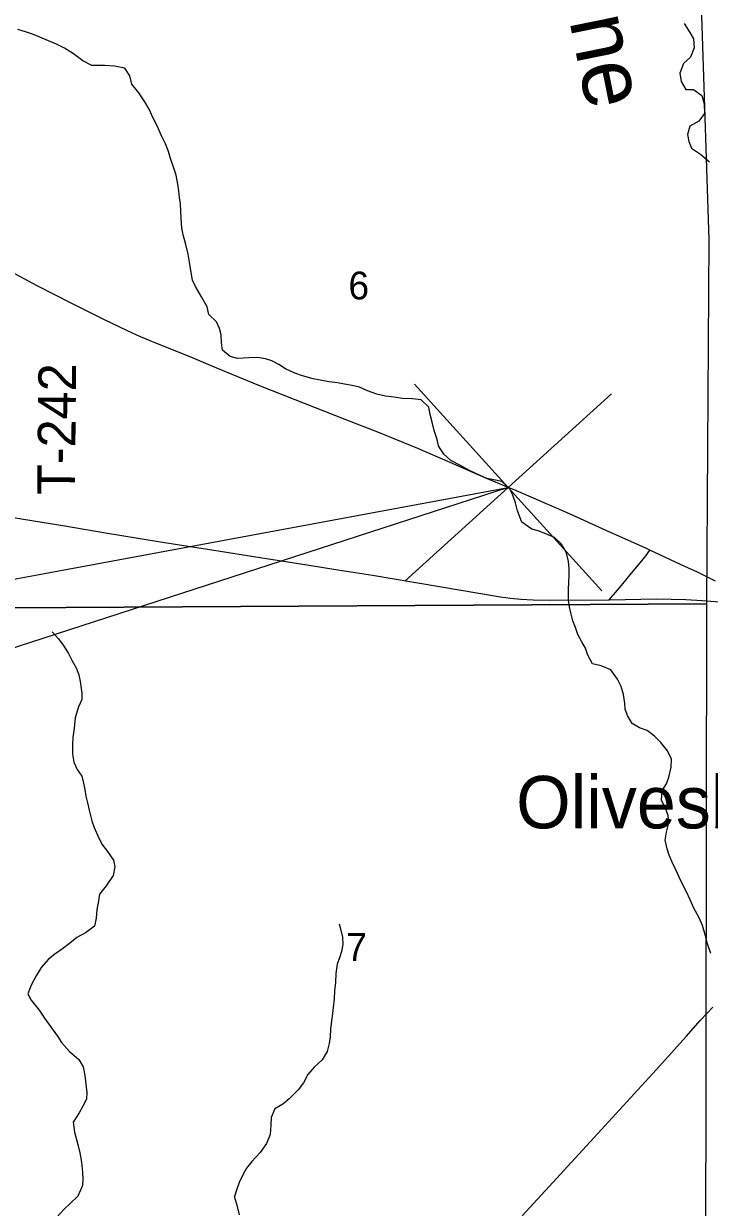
# Model space of a CAD drawing. Extents: x 0 to 70.2, y 0 to 31.4.
# Drawn here: x 4.735 to 5.768, y 16.429 to 18.211 of the extents above; entities that cross this region are included whole.
import ezdxf

# ---------------------------------------------------------------- set-up
doc = ezdxf.new("R2010")
doc.units = 0
for name, color, linetype in [('Default', 7, 'Continuous'), ('GM_X_Minor_River', 7, 'Continuous'), ('GM_X_Minor_River_Text', 7, 'Continuous'), ('GM_X_Section', 7, 'Continuous'), ('GM_X_Section_Text', 7, 'Continuous'), ('GM_X_State_Location', 7, 'Continuous'), ('GM_X_State_Route', 7, 'Continuous'), ('GM_X_Township_Road', 7, 'Continuous'), ('GM_X_Township_Road_Text', 7, 'Continuous'), ('GM_X_Unincorporated_Text', 7, 'Continuous'), ('SH_Data', 7, 'Continuous')]:
    doc.layers.add(name, color=color, linetype=linetype)

msp = doc.modelspace()

# ---------------------------------------------------------------- linework, layer by layer
at = {"layer": 'Default'}
msp.add_lwpolyline([(3.9505, 17.2317), (5.4653, 17.5125), (3.9505, 17.0217)], close=True, dxfattribs=at)
at = {"layer": 'GM_X_Minor_River'}
for points in [[(5.3537, 17.5982), (5.3508, 17.6108), (5.3478, 17.6226), (5.3459, 17.6336), (5.3342, 17.6443), (5.3213, 17.6462), (5.3058, 17.6467), (5.2933, 17.6483), (5.2804, 17.6502), (5.2675, 17.6533), (5.2535, 17.6583), (5.241, 17.6637), (5.23, 17.666), (5.2186, 17.668), (5.208, 17.6699), (5.1951, 17.6715), (5.1818, 17.6739), (5.1712, 17.6762), (5.1553, 17.6808), (5.1436, 17.6847), (5.1296, 17.6912), (5.1197, 17.6977), (5.1091, 17.7034), (5.0993, 17.7065), (5.0875, 17.7085), (5.0742, 17.7078), (5.0572, 17.7067), (5.0462, 17.7098), (5.0348, 17.7194), (5.0334, 17.7304), (5.0327, 17.7425), (5.0304, 17.752), (5.0259, 17.7619), (5.0142, 17.773), (5.0116, 17.7848), (5.0033, 17.7996), (4.9939, 17.8152), (4.9894, 17.8247), (4.9868, 17.8392), (4.985, 17.8517), (4.9832, 17.8639), (4.9794, 17.8783), (4.9753, 17.8928), (4.9735, 17.903), (4.9724, 17.9182), (4.9717, 17.9292), (4.9714, 17.9395), (4.9699, 17.9493), (4.9688, 17.9592), (4.9673, 17.9695), (4.9648, 17.9828), (4.9606, 17.9965), (4.9565, 18.0079), (4.9532, 18.0185), (4.9487, 18.0299), (4.943, 18.0421), (4.9367, 18.0562), (4.9295, 18.0699), (4.9243, 18.082), (4.9179, 18.0931), (4.9084, 18.1068), (4.8983, 18.1201), (4.8949, 18.1323), (4.8874, 18.1441), (4.8718, 18.1472), (4.8574, 18.148), (4.8377, 18.1481), (4.8241, 18.155), (4.8104, 18.1654), (4.7968, 18.1742), (4.7847, 18.1803), (4.7726, 18.1853), (4.7597, 18.1907), (4.7484, 18.1949), (4.7378, 18.1987), (4.7264, 18.2022)], [(5.7305, 18.211), (5.7391, 18.1976), (5.7448, 18.1881), (5.7458, 18.1748), (5.7401, 18.1604), (5.7294, 18.151), (5.724, 18.1366), (5.7259, 18.1237), (5.733, 18.1119), (5.7448, 18.1118), (5.7573, 18.1026), (5.7606, 18.0901), (5.7613, 18.0757), (5.7525, 18.0643), (5.7392, 18.0564), (5.7357, 18.0439), (5.7376, 18.0333), (5.7417, 18.0234), (5.7549, 18.0146), (5.7685, 18.0031)], [(5.7708, 16.8108), (5.7656, 16.8253), (5.7626, 16.8374), (5.7581, 16.853), (5.7532, 16.8644), (5.7453, 16.8793), (5.7393, 16.8914), (5.7341, 16.9036), (5.7284, 16.9143), (5.7228, 16.9257), (5.7183, 16.9356), (5.7126, 16.9485), (5.7081, 16.9588), (5.7051, 16.9683), (5.7018, 16.9816), (5.7037, 16.9933), (5.7076, 17.0074), (5.7065, 17.0184), (5.7024, 17.0294), (5.6964, 17.0412), (5.6972, 17.0564), (5.7041, 17.0662), (5.7072, 17.0765), (5.711, 17.0912), (5.7115, 17.1034), (5.7055, 17.1159), (5.6953, 17.1285), (5.6858, 17.1381), (5.6745, 17.1465), (5.6631, 17.1507), (5.6522, 17.1572), (5.645, 17.169), (5.6416, 17.1785), (5.6409, 17.188), (5.6391, 17.2009), (5.6357, 17.2131), (5.6301, 17.2237), (5.6199, 17.2378), (5.6055, 17.244), (5.5923, 17.2471), (5.5855, 17.26), (5.5818, 17.2707), (5.5765, 17.2802), (5.5701, 17.2912), (5.5667, 17.3015), (5.5626, 17.3118), (5.56, 17.3216), (5.5578, 17.333), (5.5563, 17.3429), (5.556, 17.3581), (5.5568, 17.3706), (5.5572, 17.3801), (5.5573, 17.3904), (5.5562, 17.401), (5.5525, 17.4154), (5.5457, 17.4272), (5.5351, 17.4372), (5.5222, 17.4429), (5.5105, 17.4475), (5.501, 17.4499), (5.4859, 17.4602), (5.4791, 17.4773), (5.4762, 17.4895), (5.4721, 17.5009), (5.4672, 17.5108), (5.4558, 17.5214), (5.4437, 17.5242), (5.4331, 17.5261), (5.4164, 17.5334), (5.4058, 17.5384), (5.3933, 17.5457), (5.379, 17.5533), (5.3684, 17.5625), (5.3605, 17.5754), (5.3582, 17.5849), (5.3537, 17.5982)], [(4.7782, 17.2951), (4.7876, 17.2844), (4.7944, 17.2749), (4.8027, 17.2627), (4.808, 17.2517), (4.814, 17.241), (4.8181, 17.2304), (4.8203, 17.2205), (4.8225, 17.203), (4.8225, 17.1935), (4.8179, 17.1822), (4.8125, 17.1659), (4.8113, 17.1499), (4.8093, 17.1363), (4.8085, 17.126), (4.8088, 17.1112), (4.8106, 17.0991), (4.8155, 17.0877), (4.8227, 17.0778), (4.8253, 17.0675), (4.8271, 17.058), (4.8286, 17.0477), (4.8312, 17.0375), (4.8338, 17.0268), (4.8379, 17.0105), (4.8413, 17.0006), (4.8469, 16.9881), (4.8529, 16.9755), (4.8612, 16.9645), (4.8706, 16.9511), (4.8725, 16.9412), (4.8698, 16.928), (4.8595, 16.9128), (4.8495, 16.9), (4.8472, 16.8871), (4.8456, 16.8772), (4.8444, 16.8639), (4.8417, 16.8522), (4.8284, 16.842), (4.8154, 16.8349), (4.804, 16.8258), (4.7937, 16.8179), (4.7819, 16.8096), (4.7724, 16.8024), (4.7614, 16.7899), (4.7537, 16.7771), (4.7464, 16.7631), (4.7414, 16.7502), (4.7463, 16.7403), (4.7584, 16.7254), (4.7663, 16.7132), (4.7753, 16.7007), (4.7859, 16.6862), (4.7919, 16.6767), (4.804, 16.663), (4.8184, 16.6511), (4.8248, 16.6401), (4.8274, 16.6272), (4.8303, 16.6013), (4.8298, 16.5915), (4.8245, 16.5809), (4.8187, 16.571), (4.8096, 16.5566), (4.8118, 16.5418), (4.8148, 16.5308), (4.817, 16.5213), (4.8196, 16.5107), (4.8222, 16.4966), (4.824, 16.4814), (4.8243, 16.4708), (4.8235, 16.4613), (4.8168, 16.4456)], [(5.2105, 16.8557), (5.2132, 16.8458), (5.2154, 16.8356), (5.2161, 16.8242), (5.2141, 16.8139), (5.2111, 16.8045), (5.2076, 16.7946), (5.2056, 16.7806), (5.2048, 16.7673), (5.2036, 16.7548), (5.2032, 16.7426), (5.2016, 16.7297), (5.2004, 16.7202), (5.1988, 16.7096), (5.1973, 16.6971), (5.1968, 16.6853), (5.1956, 16.6755), (5.1925, 16.6633), (5.1849, 16.6505), (5.1727, 16.6395), (5.1635, 16.6286), (5.1567, 16.6161), (5.149, 16.6055), (5.1353, 16.5922), (5.1258, 16.5839), (5.1136, 16.5768), (5.1082, 16.5639), (5.1078, 16.5521), (5.1066, 16.5381), (5.1012, 16.5245), (5.0916, 16.5112), (5.0787, 16.4976), (5.071, 16.4874), (5.0653, 16.4776), (5.0599, 16.4658), (5.0557, 16.4545), (5.0526, 16.445)], [(4.7472, 16.3027), (4.7466, 16.3086), (4.7428, 16.3215), (4.7409, 16.3314), (4.7409, 16.3435), (4.7451, 16.3576), (4.7512, 16.3682), (4.7576, 16.3777), (4.7637, 16.3875), (4.7724, 16.3989), (4.7857, 16.4145), (4.7956, 16.4255), (4.8054, 16.4342), (4.8168, 16.4456)], [(5.0602, 16.4171), (5.0571, 16.43), (5.0526, 16.445)]]:
    msp.add_lwpolyline(points, dxfattribs=at)
at = {"layer": 'GM_X_Section'}
for points in [[(4.7171, 18.3286), (4.7368, 18.3286), (5.7536, 18.3157), (5.7675, 17.8852), (5.7641, 17.3372), (4.7109, 17.3315)], [(4.7109, 17.3315), (5.7641, 17.3372), (5.7628, 16.3276), (4.7073, 16.3287)]]:
    msp.add_lwpolyline(points, close=True, dxfattribs=at)
at = {"layer": 'GM_X_State_Route'}
for points in [[(5.4812, 17.5058), (5.4317, 17.5267), (5.3776, 17.5503), (5.329, 17.571), (5.2716, 17.5947), (5.2195, 17.615), (5.1443, 17.6443), (5.0894, 17.6661), (5.0263, 17.6923), (4.9833, 17.7103), (4.9343, 17.73), (4.9113, 17.7394), (4.8914, 17.7483), (4.855, 17.7658), (4.8079, 17.7896), (4.7553, 17.8164), (4.716, 17.8372)], [(5.7779, 17.3717), (5.7668, 17.3771), (5.7578, 17.3813), (5.7494, 17.3854), (5.7326, 17.393), (5.679, 17.4183), (5.6736, 17.4208), (5.6141, 17.4475), (5.5575, 17.473), (5.5033, 17.4965), (5.4812, 17.5058)], [(4.7134, 17.4684), (4.7973, 17.4546), (4.8586, 17.4443), (4.9077, 17.4362), (4.9444, 17.43), (5.012, 17.4194), (5.101, 17.4054), (5.1655, 17.3954), (5.2085, 17.3886), (5.2606, 17.3803), (5.3617, 17.3633), (5.4536, 17.3479), (5.4689, 17.3458), (5.4843, 17.3444), (5.5029, 17.3435), (5.5277, 17.3431), (5.6177, 17.3432), (5.6892, 17.3447), (5.711, 17.3446), (5.7328, 17.3438), (5.7576, 17.3422), (5.8164, 17.3377)], [(5.4862, 16.416), (5.5326, 16.4662), (5.5831, 16.5211), (5.6883, 16.6355), (5.7338, 16.6864), (5.7544, 16.7097), (5.765, 16.7211), (5.7738, 16.7298)]]:
    msp.add_lwpolyline(points, dxfattribs=at)
at = {"layer": 'GM_X_Township_Road'}
msp.add_lwpolyline([(5.6177, 17.3432), (5.6206, 17.3469), (5.6239, 17.351), (5.6361, 17.3649), (5.651, 17.3833), (5.6691, 17.4049), (5.6747, 17.4122), (5.6763, 17.4145), (5.679, 17.4183)], dxfattribs=at)
at = {"layer": 'SH_Data'}
for p, q in [((5.6065, 17.3568), (5.3241, 17.6682)), ((5.3096, 17.3713), (5.6211, 17.6537))]:
    msp.add_line(p, q, dxfattribs=at)

# ---------------------------------------------------------------- texts
at = {"layer": 'GM_X_Minor_River_Text'}
msp.add_text('Whetstone', height=0.09474, rotation=281.4771, dxfattribs=at).set_placement((5.4648, 18.6713))
at = {"layer": 'GM_X_Section_Text'}
for s, p in [('6', (5.2245, 17.7957)), ('7', (5.2212, 16.7996))]:
    msp.add_text(s, height=0.0419, rotation=0, dxfattribs=at).set_placement(p)
at = {"layer": 'GM_X_State_Location'}
for s in ['s', 'r']:
    msp.add_text(s, height=0.000189, dxfattribs=at).set_placement((5.423, 17.5081))
msp.add_text('603', height=0.000189, rotation=0, dxfattribs=at).set_placement((5.3562, 17.4943))
at = {"layer": 'GM_X_Township_Road_Text'}
msp.add_text('T-242', height=0.05682, rotation=89.4382, dxfattribs=at).set_placement((4.8123, 17.5008))
at = {"layer": 'GM_X_Unincorporated_Text'}
msp.add_text('Olivesburg', height=0.07898, rotation=0, dxfattribs=at).set_placement((5.4773, 16.9992))

doc.saveas('drawing.dxf')
